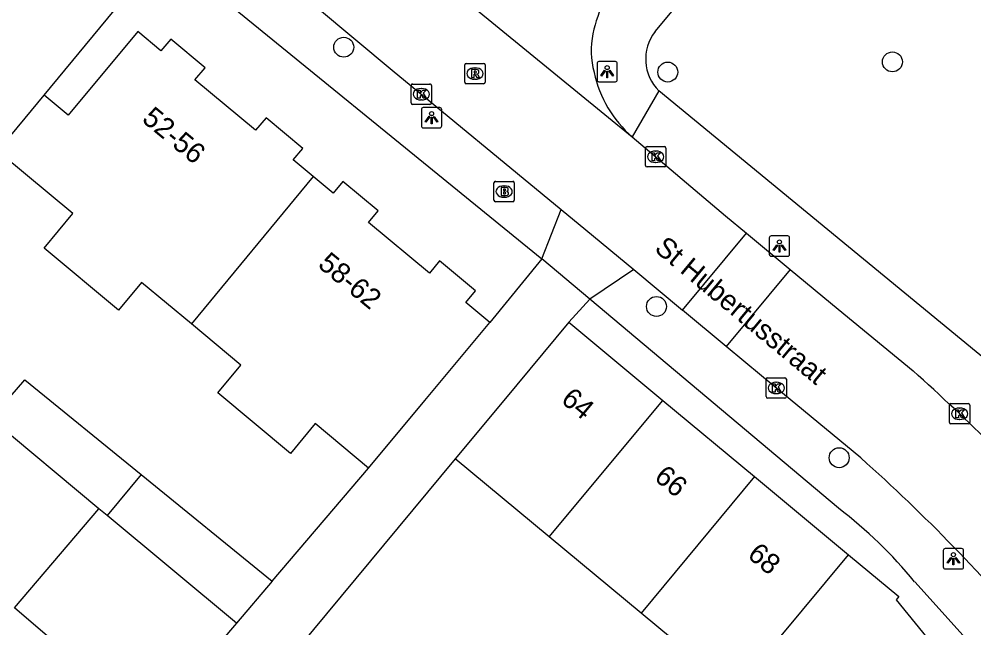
# Model space of a CAD drawing. Extents: x 162074 to 163034, y 381824 to 382557.
# Drawn here: x 162432.01 to 162478.91, y 381943.68 to 381973.59 of the extents above; entities that cross this region are included whole.
import ezdxf

# ---------------------------------------------------------------- set-up
doc = ezdxf.new("R2010")
doc.units = 0
for name, color, linetype in [('IMGEO_Boom', 7, 'Continuous'), ('IMGEO_Brandkraan', 7, 'Continuous'), ('IMGEO_Kolk', 7, 'Continuous'), ('IMGEO_Lichtpunt', 7, 'Continuous'), ('IMGEO_Openbare_ruimte_label', 7, 'Continuous'), ('IMGEO_Pand', 7, 'Continuous'), ('IMGEO_Pand_nummerreeks', 7, 'Continuous'), ('IMGEO_Rijbaan_lokaal_open', 7, 'Continuous'), ('IMGEO_Rioolput', 7, 'Continuous'), ('IMGEO_Voetpad_open', 7, 'Continuous')]:
    doc.layers.add(name, color=color, linetype=linetype)

msp = doc.modelspace()

# ---------------------------------------------------------------- linework, layer by layer
at = {"layer": 'IMGEO_Boom'}
for centre in [(162447.954, 381972.205), (162474.904, 381971.484), (162463.869, 381970.984), (162463.314, 381959.47), (162472.288, 381952.042)]:
    msp.add_circle(centre, 0.489, dxfattribs=at)
at = {"layer": 'IMGEO_Brandkraan'}
for p, q in [((162455.331, 381964.691), (162455.331, 381965.543)), ((162455.406, 381965.617), (162456.258, 381965.617)), ((162455.819, 381965.397), (162455.844, 381965.397)), ((162456.332, 381965.543), (162456.332, 381964.691)), ((162456.258, 381964.617), (162455.406, 381964.617)), ((162455.842, 381964.837), (162455.817, 381964.837))]:
    msp.add_line(p, q, dxfattribs=at)
for points in [[(162455.331, 381964.691), (162455.331, 381965.543)], [(162455.406, 381965.617), (162456.258, 381965.617)], [(162456.332, 381965.543), (162456.332, 381964.691)], [(162455.679, 381965.317), (162455.679, 381964.917), (162455.892, 381964.917)], [(162455.91, 381965.317), (162455.679, 381965.317)], [(162455.858, 381965.236), (162455.804, 381965.236), (162455.804, 381965.16)], [(162455.804, 381965.16), (162455.857, 381965.16)], [(162455.866, 381965.084), (162455.804, 381965.084), (162455.804, 381965.003)], [(162455.804, 381965.003), (162455.866, 381965.003)], [(162456.258, 381964.617), (162455.406, 381964.617)]]:
    msp.add_lwpolyline(points, dxfattribs=at)
for centre, radius, start, end in [((162455.408, 381965.541), 0.0765, 91.552, 178.448), ((162455.408, 381965.541), 0.0765, 91.552, 178.448), ((162456.256, 381965.541), 0.0765, 1.552, 88.448), ((162456.256, 381965.541), 0.0765, 1.552, 88.448), ((162455.859, 381965.198), 0.0379, 267.8285, 90.9355), ((162455.867, 381965.043), 0.0404, 269.8759, 90.5077), ((162455.898, 381965.168), 0.251, 268.6676, 293.5347), ((162455.914, 381965.172), 0.145, 59.4692, 91.5367), ((162455.939, 381965.219), 0.0922, 285.5137, 58.1501), ((162455.944, 381965.027), 0.105, 301.3115, 78.989), ((162455.408, 381964.693), 0.0765, 181.552, 268.448), ((162455.408, 381964.693), 0.0765, 181.552, 268.448), ((162456.256, 381964.693), 0.0765, 271.552, 358.448), ((162456.256, 381964.693), 0.0765, 271.552, 358.448)]:
    msp.add_arc(centre, radius, start, end, dxfattribs=at)
for centre, major_axis, ratio, start_param, end_param in [((162455.818, 381965.117), (-0.387, 0.002), 0.722429, 4.712389, 7.853982), ((162455.843, 381965.117), (-0.39, 0.002), 0.717154, 1.570796, 4.712389)]:
    msp.add_ellipse(centre, major_axis=major_axis, ratio=ratio, start_param=start_param, end_param=end_param, dxfattribs=at)
at = {"layer": 'IMGEO_Kolk'}
for p, q in [((162451.262, 381969.472), (162451.262, 381970.324)), ((162451.337, 381970.398), (162452.189, 381970.398)), ((162451.75, 381970.178), (162451.775, 381970.178)), ((162452.263, 381970.324), (162452.263, 381969.472)), ((162451.773, 381969.618), (162451.748, 381969.618)), ((162452.189, 381969.398), (162451.337, 381969.398)), ((162462.776, 381966.397), (162462.776, 381967.249)), ((162462.851, 381967.323), (162463.703, 381967.323)), ((162463.777, 381967.249), (162463.777, 381966.397)), ((162463.264, 381967.103), (162463.289, 381967.103)), ((162463.703, 381966.323), (162462.851, 381966.323)), ((162463.287, 381966.543), (162463.262, 381966.543)), ((162468.772, 381955.968), (162469.624, 381955.968)), ((162468.697, 381955.042), (162468.697, 381955.894)), ((162469.185, 381955.748), (162469.21, 381955.748)), ((162469.698, 381955.894), (162469.698, 381955.042)), ((162469.208, 381955.188), (162469.183, 381955.188)), ((162469.624, 381954.968), (162468.772, 381954.968)), ((162477.704, 381953.773), (162477.704, 381954.625)), ((162477.779, 381954.699), (162478.631, 381954.699)), ((162478.705, 381954.625), (162478.705, 381953.773)), ((162478.192, 381954.479), (162478.217, 381954.479)), ((162478.631, 381953.699), (162477.779, 381953.699)), ((162478.215, 381953.919), (162478.19, 381953.919))]:
    msp.add_line(p, q, dxfattribs=at)
for points in [[(162451.262, 381969.472), (162451.262, 381970.324)], [(162451.337, 381970.398), (162452.189, 381970.398)], [(162451.583, 381970.098), (162451.706, 381970.098), (162451.706, 381969.947), (162451.836, 381970.098), (162452, 381970.098), (162451.854, 381969.947), (162452.007, 381969.698), (162451.855, 381969.698), (162451.77, 381969.862), (162451.706, 381969.795), (162451.706, 381969.698), (162451.583, 381969.698), (162451.583, 381970.098)], [(162452.263, 381970.324), (162452.263, 381969.472)], [(162452.189, 381969.398), (162451.337, 381969.398)], [(162462.776, 381966.397), (162462.776, 381967.249)], [(162462.851, 381967.323), (162463.703, 381967.323)], [(162463.777, 381967.249), (162463.777, 381966.397)], [(162463.097, 381967.023), (162463.22, 381967.023), (162463.22, 381966.872), (162463.35, 381967.023), (162463.514, 381967.023), (162463.368, 381966.872), (162463.521, 381966.623), (162463.369, 381966.623), (162463.284, 381966.787), (162463.22, 381966.72), (162463.22, 381966.623), (162463.097, 381966.623), (162463.097, 381967.023)], [(162463.703, 381966.323), (162462.851, 381966.323)], [(162468.772, 381955.968), (162469.624, 381955.968)], [(162468.697, 381955.042), (162468.697, 381955.894)], [(162469.018, 381955.668), (162469.141, 381955.668), (162469.141, 381955.517), (162469.271, 381955.668), (162469.435, 381955.668), (162469.289, 381955.517), (162469.442, 381955.268), (162469.29, 381955.268), (162469.205, 381955.432), (162469.141, 381955.365), (162469.141, 381955.268), (162469.018, 381955.268), (162469.018, 381955.668)], [(162469.698, 381955.894), (162469.698, 381955.042)], [(162469.624, 381954.968), (162468.772, 381954.968)], [(162477.704, 381953.773), (162477.704, 381954.625)], [(162477.779, 381954.699), (162478.631, 381954.699)], [(162478.705, 381954.625), (162478.705, 381953.773)], [(162478.025, 381954.399), (162478.148, 381954.399), (162478.148, 381954.248), (162478.278, 381954.399), (162478.442, 381954.399), (162478.296, 381954.248), (162478.449, 381953.999), (162478.297, 381953.999), (162478.212, 381954.163), (162478.148, 381954.096), (162478.148, 381953.999), (162478.025, 381953.999), (162478.025, 381954.399)], [(162478.631, 381953.699), (162477.779, 381953.699)]]:
    msp.add_lwpolyline(points, dxfattribs=at)
for centre, start, end in [((162451.339, 381970.322), 91.552, 178.448), ((162451.339, 381970.322), 91.552, 178.448), ((162452.187, 381970.322), 1.552, 88.448), ((162452.187, 381970.322), 1.552, 88.448), ((162451.339, 381969.474), 181.552, 268.448), ((162451.339, 381969.474), 181.552, 268.448), ((162452.187, 381969.474), 271.552, 358.448), ((162452.187, 381969.474), 271.552, 358.448), ((162462.853, 381967.247), 91.552, 178.448), ((162462.853, 381967.247), 91.552, 178.448), ((162463.701, 381967.247), 1.552, 88.448), ((162463.701, 381967.247), 1.552, 88.448), ((162462.853, 381966.399), 181.552, 268.448), ((162462.853, 381966.399), 181.552, 268.448), ((162463.701, 381966.399), 271.552, 358.448), ((162463.701, 381966.399), 271.552, 358.448), ((162468.774, 381955.892), 91.552, 178.448), ((162468.774, 381955.892), 91.552, 178.448), ((162469.622, 381955.892), 1.552, 88.448), ((162469.622, 381955.892), 1.552, 88.448), ((162468.774, 381955.044), 181.552, 268.448), ((162468.774, 381955.044), 181.552, 268.448), ((162469.622, 381955.044), 271.552, 358.448), ((162469.622, 381955.044), 271.552, 358.448), ((162477.781, 381954.623), 91.552, 178.448), ((162477.781, 381954.623), 91.552, 178.448), ((162478.629, 381954.623), 1.552, 88.448), ((162478.629, 381954.623), 1.552, 88.448), ((162477.781, 381953.775), 181.552, 268.448), ((162477.781, 381953.775), 181.552, 268.448), ((162478.629, 381953.775), 271.552, 358.448), ((162478.629, 381953.775), 271.552, 358.448)]:
    msp.add_arc(centre, 0.0765, start, end, dxfattribs=at)
for centre, major_axis, ratio, start_param, end_param in [((162451.749, 381969.898), (-0.387, 0.002), 0.722429, 4.712389, 7.853982), ((162451.774, 381969.898), (-0.39, 0.002), 0.717154, 1.570796, 4.712389), ((162463.263, 381966.823), (-0.387, 0.002), 0.722429, 4.712389, 7.853982), ((162463.288, 381966.823), (-0.39, 0.002), 0.717154, 1.570796, 4.712389), ((162469.184, 381955.468), (-0.387, 0.002), 0.722429, 4.712389, 7.853982), ((162469.209, 381955.468), (-0.39, 0.002), 0.717154, 1.570796, 4.712389), ((162478.191, 381954.199), (-0.387, 0.002), 0.722429, 4.712389, 7.853982), ((162478.216, 381954.199), (-0.39, 0.002), 0.717154, 1.570796, 4.712389)]:
    msp.add_ellipse(centre, major_axis=major_axis, ratio=ratio, start_param=start_param, end_param=end_param, dxfattribs=at)
at = {"layer": 'IMGEO_Lichtpunt'}
for p, q in [((162461.296, 381971.502), (162460.488, 381971.502)), ((162461.296, 381971.502), (162460.488, 381971.502)), ((162460.394, 381971.407), (162460.394, 381970.6)), ((162460.394, 381971.407), (162460.394, 381970.6)), ((162461.39, 381970.6), (162461.39, 381971.407)), ((162461.39, 381970.6), (162461.39, 381971.407)), ((162460.488, 381970.506), (162461.296, 381970.506)), ((162460.488, 381970.506), (162461.296, 381970.506)), ((162451.769, 381969.147), (162451.769, 381968.34)), ((162451.769, 381969.147), (162451.769, 381968.34)), ((162452.671, 381969.242), (162451.863, 381969.242)), ((162452.671, 381969.242), (162451.863, 381969.242)), ((162452.765, 381968.34), (162452.765, 381969.147)), ((162452.765, 381968.34), (162452.765, 381969.147)), ((162451.863, 381968.246), (162452.671, 381968.246)), ((162451.863, 381968.246), (162452.671, 381968.246)), ((162468.857, 381962.842), (162468.857, 381962.035)), ((162468.857, 381962.842), (162468.857, 381962.035)), ((162469.759, 381962.937), (162468.951, 381962.937)), ((162469.759, 381962.937), (162468.951, 381962.937)), ((162469.853, 381962.035), (162469.853, 381962.842)), ((162469.853, 381962.035), (162469.853, 381962.842)), ((162468.951, 381961.941), (162469.759, 381961.941)), ((162468.951, 381961.941), (162469.759, 381961.941)), ((162478.304, 381947.577), (162477.496, 381947.577)), ((162478.304, 381947.577), (162477.496, 381947.577)), ((162477.402, 381947.482), (162477.402, 381946.675)), ((162477.402, 381947.482), (162477.402, 381946.675)), ((162478.398, 381946.675), (162478.398, 381947.482)), ((162478.398, 381946.675), (162478.398, 381947.482)), ((162477.496, 381946.581), (162478.304, 381946.581)), ((162477.496, 381946.581), (162478.304, 381946.581))]:
    msp.add_line(p, q, dxfattribs=at)
for points in [[(162460.768, 381971.071), (162460.807, 381971.043), (162460.619, 381970.781), (162460.581, 381970.808), (162460.768, 381971.071)], [(162460.87, 381971.023), (162460.917, 381971.023), (162460.917, 381970.701), (162460.87, 381970.701), (162460.87, 381971.023)], [(162460.98, 381971.043), (162461.018, 381971.07), (162461.205, 381970.808), (162461.166, 381970.78), (162460.98, 381971.043)], [(162452.143, 381968.811), (162452.182, 381968.783), (162451.994, 381968.521), (162451.956, 381968.548), (162452.143, 381968.811)], [(162452.245, 381968.763), (162452.292, 381968.763), (162452.292, 381968.441), (162452.245, 381968.441), (162452.245, 381968.763)], [(162452.355, 381968.783), (162452.393, 381968.81), (162452.58, 381968.548), (162452.541, 381968.52), (162452.355, 381968.783)], [(162469.231, 381962.506), (162469.27, 381962.478), (162469.082, 381962.216), (162469.044, 381962.243), (162469.231, 381962.506)], [(162469.333, 381962.458), (162469.38, 381962.458), (162469.38, 381962.136), (162469.333, 381962.136), (162469.333, 381962.458)], [(162469.443, 381962.478), (162469.481, 381962.505), (162469.668, 381962.243), (162469.629, 381962.215), (162469.443, 381962.478)], [(162477.776, 381947.146), (162477.815, 381947.118), (162477.627, 381946.856), (162477.589, 381946.883), (162477.776, 381947.146)], [(162477.878, 381947.098), (162477.925, 381947.098), (162477.925, 381946.776), (162477.878, 381946.776), (162477.878, 381947.098)], [(162477.988, 381947.118), (162478.026, 381947.145), (162478.213, 381946.883), (162478.174, 381946.855), (162477.988, 381947.118)]]:
    msp.add_lwpolyline(points, dxfattribs=at)
for centre in [(162460.893, 381971.205), (162452.268, 381968.945), (162469.356, 381962.64), (162477.901, 381947.28)]:
    msp.add_circle(centre, 0.0994, dxfattribs=at)
for centre, start, end in [((162460.488, 381971.407), 90, 180), ((162460.488, 381971.407), 90, 180), ((162461.296, 381971.407), 0, 90), ((162461.296, 381971.407), 0, 90), ((162460.488, 381970.6), 180, 270), ((162460.488, 381970.6), 180, 270), ((162461.296, 381970.6), 270, 0), ((162461.296, 381970.6), 270, 360), ((162451.863, 381969.147), 90, 180), ((162451.863, 381969.147), 90, 180), ((162452.671, 381969.147), 0, 90), ((162452.671, 381969.147), 0, 90), ((162451.863, 381968.34), 180, 270), ((162451.863, 381968.34), 180, 270), ((162452.671, 381968.34), 270, 0), ((162452.671, 381968.34), 270, 360), ((162468.951, 381962.842), 90, 180), ((162468.951, 381962.842), 90, 180), ((162469.759, 381962.842), 0, 90), ((162469.759, 381962.842), 0, 90), ((162468.951, 381962.035), 180, 270), ((162468.951, 381962.035), 180, 270), ((162469.759, 381962.035), 270, 0), ((162469.759, 381962.035), 270, 360), ((162477.496, 381947.482), 90, 180), ((162477.496, 381947.482), 90, 180), ((162478.304, 381947.482), 0, 90), ((162478.304, 381947.482), 0, 90), ((162477.496, 381946.675), 180, 270), ((162477.496, 381946.675), 180, 270), ((162478.304, 381946.675), 270, 0), ((162478.304, 381946.675), 270, 360)]:
    msp.add_arc(centre, 0.0946, start, end, dxfattribs=at)
at = {"layer": 'IMGEO_Pand'}
for points in [[(162446.447, 381965.854), (162445.468, 381966.668), (162445.942, 381967.238), (162444.138, 381968.738), (162443.626, 381968.123), (162440.646, 381970.602), (162441.141, 381971.197), (162439.455, 381972.599), (162438.976, 381972.025), (162437.834, 381972.975), (162434.415, 381968.865), (162433.232, 381969.849)], [(162431.162, 381966.941), (162430.956, 381967.113), (162433.232, 381969.849)], [(162440.468, 381958.617), (162438.018, 381960.655), (162436.887, 381959.295), (162433.235, 381962.332), (162434.654, 381964.038), (162431.162, 381966.941)], [(162446.447, 381965.854), (162440.468, 381958.617)], [(162455.127, 381958.689), (162453.947, 381959.671), (162454.42, 381960.239), (162452.656, 381961.706), (162452.162, 381961.113), (162449.173, 381963.6), (162449.644, 381964.166), (162447.905, 381965.613), (162447.427, 381965.039), (162446.447, 381965.854)], [(162449.175, 381951.535), (162446.549, 381953.719), (162445.331, 381952.255), (162441.763, 381955.223), (162442.902, 381956.592), (162440.468, 381958.617)], [(162449.175, 381951.535), (162451.93, 381954.846), (162455.127, 381958.689)], [(162459.016, 381958.698), (162455.819, 381954.855), (162453.434, 381951.988)], [(162459.016, 381958.698), (162463.63, 381954.859)], [(162435.925, 381949.539), (162430.618, 381953.956), (162432.288, 381955.875), (162438, 381951.219)], [(162458.052, 381948.153), (162463.63, 381954.859)], [(162463.63, 381954.859), (162468.132, 381951.115)], [(162458.052, 381948.153), (162453.434, 381951.988)], [(162438, 381951.219), (162436.333, 381949.2)], [(162438, 381951.219), (162444.436, 381945.975)], [(162468.132, 381951.115), (162462.557, 381944.412)], [(162468.132, 381951.115), (162472.75, 381947.274)], [(162435.703, 381941.319), (162431.774, 381944.667), (162435.925, 381949.539)], [(162436.333, 381949.2), (162435.925, 381949.539)], [(162442.682, 381943.917), (162436.333, 381949.2)], [(162462.557, 381944.412), (162458.052, 381948.153)], [(162467.176, 381940.577), (162472.75, 381947.274)], [(162472.75, 381947.274), (162475.216, 381945.222), (162475.088, 381945.068), (162478.463, 381940.914)], [(162444.436, 381945.975), (162442.682, 381943.917)], [(162467.176, 381940.577), (162462.557, 381944.412)], [(162442.682, 381943.917), (162438.464, 381938.967)]]:
    msp.add_lwpolyline(points, dxfattribs=at)
at = {"layer": 'IMGEO_Rijbaan_lokaal_open'}
for points in [[(162440.82, 381979.014), (162441.112, 381978.783), (162450.335, 381971.078), (162458.638, 381964.23)], [(162450.399, 381977.405), (162462.125, 381967.796)], [(162462.125, 381967.796), (162466.711, 381963.919), (162467.73, 381963.075)], [(162458.638, 381964.23), (162459.847, 381963.233), (162462.198, 381961.281)], [(162464.587, 381959.297), (162467.73, 381963.075)], [(162467.73, 381963.075), (162469.887, 381961.289)], [(162457.681, 381961.808), (162455.127, 381958.689)], [(162460.043, 381959.824), (162457.681, 381961.808)], [(162462.198, 381961.281), (162464.587, 381959.297)], [(162469.887, 381961.289), (162466.742, 381957.508)], [(162469.887, 381961.289), (162472.237, 381959.344), (162475.922, 381956.303)], [(162460.043, 381959.824), (162459.016, 381958.698)], [(162466.742, 381957.508), (162464.587, 381959.297)], [(162473.355, 381952.029), (162468.478, 381956.066), (162466.742, 381957.508)], [(162453.434, 381951.988), (162445.748, 381942.733), (162447.904, 381940.882)], [(162444.436, 381945.975), (162449.175, 381951.535)]]:
    msp.add_lwpolyline(points, dxfattribs=at)
for centre, radius, start, end in [((162467.252, 381971.38), 7.214, 140.2638, 168.0837), ((162464.339, 381972.038), 4.229, 168.649, 194.6086), ((162466.041, 381972.255), 5.935, 192.4986, 228.7097), ((162412.964, 381885.765), 94.548, 41.63844, 48.2501), ((162415.641, 381887.258), 86.754, 39.9668, 48.2971)]:
    msp.add_arc(centre, radius, start, end, dxfattribs=at)
at = {"layer": 'IMGEO_Rioolput'}
for p, q in [((162453.897, 381970.486), (162453.897, 381971.338)), ((162453.972, 381971.412), (162454.824, 381971.412)), ((162454.385, 381971.192), (162454.41, 381971.192)), ((162454.898, 381971.338), (162454.898, 381970.486)), ((162454.408, 381970.632), (162454.383, 381970.632)), ((162454.824, 381970.412), (162453.972, 381970.412))]:
    msp.add_line(p, q, dxfattribs=at)
for points in [[(162453.897, 381970.486), (162453.897, 381971.338)], [(162453.972, 381971.412), (162454.824, 381971.412)], [(162454.486, 381971.11), (162454.234, 381971.112), (162454.234, 381970.712)], [(162454.412, 381971.031), (162454.358, 381971.031), (162454.358, 381970.95)], [(162454.898, 381971.338), (162454.898, 381970.486)], [(162454.234, 381970.712), (162454.358, 381970.712), (162454.358, 381970.874), (162454.369, 381970.874)], [(162454.358, 381970.95), (162454.41, 381970.95)], [(162454.416, 381970.845), (162454.487, 381970.712), (162454.627, 381970.712), (162454.562, 381970.838)], [(162454.824, 381970.412), (162453.972, 381970.412)]]:
    msp.add_lwpolyline(points, dxfattribs=at)
for centre, radius, start, end in [((162453.974, 381971.336), 0.0765, 91.552, 178.448), ((162453.974, 381971.336), 0.0765, 91.552, 178.448), ((162454.418, 381970.935), 0.0964, 77.0061, 93.1865), ((162454.432, 381970.992), 0.0378, 276.6634, 79.6772), ((162454.485, 381971), 0.109, 350.3612, 89.416), ((162454.483, 381971), 0.112, 277.5842, 350.9817), ((162454.822, 381971.336), 0.0765, 1.552, 88.448), ((162454.822, 381971.336), 0.0765, 1.552, 88.448), ((162454.368, 381970.821), 0.0533, 26.0293, 88.6989), ((162454.394, 381971.139), 0.19, 274.7715, 282.9687), ((162454.467, 381970.785), 0.108, 29.5134, 73.7905), ((162453.974, 381970.488), 0.0765, 181.552, 268.448), ((162453.974, 381970.488), 0.0765, 181.552, 268.448), ((162454.822, 381970.488), 0.0765, 271.552, 358.448), ((162454.822, 381970.488), 0.0765, 271.552, 358.448)]:
    msp.add_arc(centre, radius, start, end, dxfattribs=at)
for centre, major_axis, ratio, start_param, end_param in [((162454.384, 381970.912), (-0.387, 0.002), 0.722429, 4.712389, 7.853982), ((162454.409, 381970.912), (-0.39, 0.002), 0.717154, 1.570796, 4.712389)]:
    msp.add_ellipse(centre, major_axis=major_axis, ratio=ratio, start_param=start_param, end_param=end_param, dxfattribs=at)
at = {"layer": 'IMGEO_Voetpad_open'}
for points in [[(162463.245, 381972.97), (162479.39, 381992.322), (162485.8, 382000), (162496.617, 382012.958)], [(162433.232, 381969.849), (162439.099, 381976.949)], [(162439.099, 381976.949), (162457.681, 381961.808)], [(162463.437, 381970.058), (162462.125, 381967.796)], [(162482.072, 381954.546), (162480.038, 381956.402), (162463.437, 381970.058)], [(162457.681, 381961.808), (162458.638, 381964.23)], [(162462.198, 381961.281), (162460.043, 381959.824)], [(162472.261, 381949.557), (162460.043, 381959.824)], [(162524.728, 381886.592), (162523.779, 381887.754), (162520.879, 381891.323), (162500, 381916.926), (162479.554, 381941.998), (162475.997, 381945.948)]]:
    msp.add_lwpolyline(points, dxfattribs=at)
for centre, radius, start, end in [((162464.985, 381971.622), 2.201, 142.2485, 225.296), ((162458.514, 381931.588), 22.624, 39.3986, 52.5826)]:
    msp.add_arc(centre, radius, start, end, dxfattribs=at)

# ---------------------------------------------------------------- texts
at = {"layer": 'IMGEO_Openbare_ruimte_label'}
msp.add_text('St Hubertusstraat', height=1, rotation=320.2751, dxfattribs=at).set_placement((162463.161, 381962.228))
at = {"layer": 'IMGEO_Pand_nummerreeks'}
for s, rotation, p in [('52-56', 320.4166, (162437.988, 381968.591)), ('58-62', 320.462, (162446.633, 381961.447)), ('64', 320.2446, (162458.572, 381954.801)), ('66', 320.2446, (162463.15, 381950.993)), ('68', 320.2446, (162467.73, 381947.183))]:
    msp.add_text(s, height=1, rotation=rotation, dxfattribs=at).set_placement(p)

doc.saveas('drawing.dxf')
